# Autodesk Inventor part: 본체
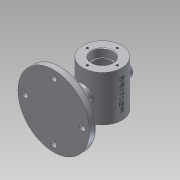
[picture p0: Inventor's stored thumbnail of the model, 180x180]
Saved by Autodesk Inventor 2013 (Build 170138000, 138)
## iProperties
Created: 2018-12
Part Number: 본체
Material: 알루미늄 6061
Document SubType Name: Modeling
Designer: Administrator
Mass: 687.623 g
Surface Area: 555.459 cm^2
Volume: 253.735 cm^3
Density: 2.71 g/cm^3
Author: Administrator
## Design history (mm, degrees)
sketch "스케치1"
  geometry: C1 r 30 at (0, 0); 1 further point
  constraints: 1 centre point, 1 coincident
  dimensions: "d0" = 60 diameter of C1
extrude "돌출1" new body sketch "스케치1" stored distance "d2" = 70; taper "d3" = 0 deg
sketch "스케치2"
  geometry: C1 r 30 at (0, 0) reference
hole "구멍1" sketch "스케치2" at (0, 0) diameter "d4" = 28; stored, may be unused: countersink angle "d8" = 90 deg, drill point angle "d10" = 0 deg; dims "d5" = 6, "d6" = 32, "d7" = 12, "d9" = 15
sketch "스케치3"
  geometry: C1 r 14 at (0, 0) reference; C2 r 25 at (0, 0)
  constraints: 1 centre point, 1 coincident
  dimensions: "d11" = 50 diameter of C2
extrude "돌출2" cut sketch "스케치3" distance "d13" = 40; taper "d14" = 0 deg
sketch "스케치4"
  geometry: C1 r 16 at (0, 0) reference; 1 further point
  constraints: 1 vertical alignment
  dimensions: "d15" = 23 distance of C1.centre point (0, 23)
hole "구멍2" sketch "스케치4" at (0, 23) diameter "d16" = 3.242; stored, may be unused: countersink angle "d20" = 90 deg, drill point angle "d22" = 118 deg; dims "d17" = 8, "d18" = 32, "d19" = 12, "d21" = 10
node "작업 평면1"
sketch "스케치5"
  geometry: C1 r 55 at (0, 0); 1 further point
  constraints: 1 centre point, 1 coincident
  dimensions: "d27" = 110 diameter of C1
extrude "돌출3" join sketch "스케치5" distance "d29" = 11; taper "d30" = 0 deg
sketch "스케치6"
  geometry: L1 (55, -64)-(-55, -64) reference; L2 (55, -64)-(12, -52.478); L3 (12, -52.478)-(0, -52.478); L4 (0, -52.478)-(0, -64); L5 (55, -75)-(55, -64) reference; 1 further point
  constraints: 6 end point, 1 midpoint, 1 parallel, 1 perpendicular, 1 vertical alignment
  dimensions: "d31" = 75 deg angle of L5 L2; "d32" = 12 distance of L2.end L3.end
revolve "회전1" sketch "스케치6" stored, may be unused: angle "d34" = 90 deg
sketch "스케치7"
  geometry: C1 r 12 at (0, 0) reference
extrude "돌출4" join sketch "스케치7" stored distance "d35" = 11; taper "d36" = 0 deg
node "작업 평면2"
sketch "스케치8"
  geometry: C1 r 10 at (0, 0); 1 further point
  constraints: 1 centre point, 1 coincident
  dimensions: "d38" = 20 diameter of C1
extrude "돌출5" join sketch "스케치8" stored distance "d40" = 11; taper "d41" = 0 deg
hole "구멍3" diameter "d44" = 10; stored, may be unused: countersink angle "d48" = 90 deg, drill point angle "d50" = 0 deg; dims "d42" = 10, "d43" = 10, "d45" = 8, "d46" = 32, "d47" = 12, "d49" = 10
node "작업 평면3"
sketch "스케치9"
  geometry: L1 (30, 35)-(-30, 35) reference; L2 (30, -35)-(30, 35) reference; 2 further points
  constraints: 1 other
  dimensions: "d52" = 35 distance from line of L1 point (0, 0); "d53" = 30 distance from line of point (0, 0) L2
feature "엠보싱1" sketch "스케치9" dims "d54" = 0.5, "d55" = 0
chamfer "모따기1" distance "d56" = 1; stored, may be unused: second distance "d57" = 2, angle "d58" = 45 deg
fillet "모깎기1" dims "d59" = 0.3
fillet "모깎기2" dims "d60" = 3
fillet "모깎기3" dims "d61" = 3
sketch "스케치10" dims "d62" = 88
  geometry: C1 r 55 at (0, 0) reference; C2 r 4.5 at (0, 44); 1 further point
  constraints: 2 vertical alignment, 1 centre point, 1 coincident, 2 other
  dimensions: "d64" = 9 diameter of C2
extrude "돌출6" cut sketch "스케치10" stored distance "d65" = 11; taper "d66" = 0 deg
node "작업 평면4"
sketch "스케치11"
  geometry: C1 r 7 at (0, 44); 3 further points
  constraints: 1 centre point, 1 vertical alignment, 3 other
  dimensions: "d68" = 14 diameter of C1
extrude "돌출7" cut sketch "스케치11" stored distance "d70" = 11; taper "d71" = 0 deg
node "솔리드1"
mirror "대칭1"
pattern_circular "원형 패턴1" dims angle "d24" = 360 deg
mirror "대칭2"
pattern_circular "원형 패턴2" dims angle "d73" = 360 deg
other parameters: "d26" = -75, "d37" = -112
